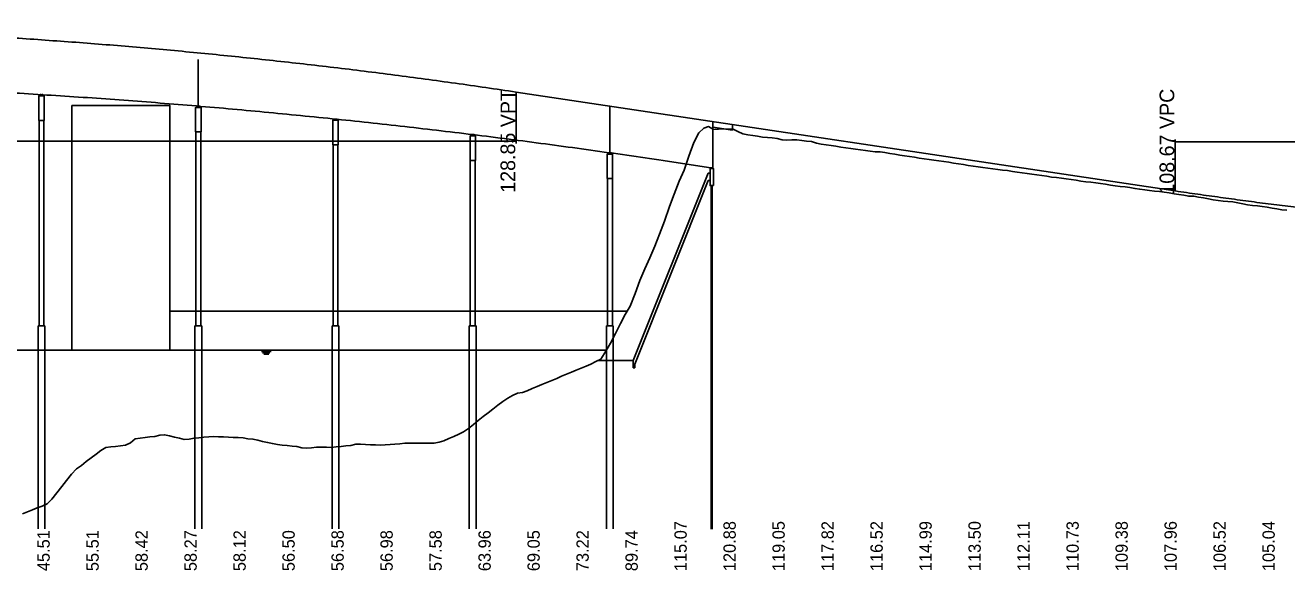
# Model space of a CAD drawing. Extents: x 2121671 to 2169879, y 557274 to 599957.
# Drawn here: x 2155742 to 2157029, y 595763 to 596320 of the extents above; entities that cross this region are included whole.
import ezdxf

# ---------------------------------------------------------------- set-up
doc = ezdxf.new("R2010")
doc.units = 0
for name, color, linetype in [('BR_CONCRETE', 7, 'Continuous'), ('BR_DETAILS', 7, 'Continuous'), ('BR_PRESTRESSED BEAM', 7, 'Continuous'), ('BR_STRUCTURAL STEEL', 7, 'Continuous'), ('RD_DDB_Profile_Elev', 7, 'Continuous'), ('RD_DDB_Profile_EX', 7, 'Continuous'), ('RD_DDB_Profile_PR', 7, 'Continuous'), ('RD_DDB_StripGrade', 7, 'Continuous'), ('RD_DDB_VCLbl', 7, 'Continuous')]:
    doc.layers.add(name, color=color, linetype=linetype)

msp = doc.modelspace()

# ---------------------------------------------------------------- linework, layer by layer
at = {"layer": 'BR_CONCRETE'}
for p, q in [((2155756.3, 596222.8), (2155756.3, 596013.1)), ((2155761.3, 596222.8), (2155761.3, 596013.1)), ((2156443.8, 596215.8), (2156463.8, 596212.8)), ((2156463.8, 596212.8), (2156463.8, 596218.6)), ((2155916.3, 596211.1), (2155916.3, 596013.1)), ((2155921.3, 596211.1), (2155921.3, 596013.1)), ((2156056.3, 596197.9), (2156056.3, 596013.1)), ((2156061.3, 596197.9), (2156061.3, 596013.1)), ((2156196.3, 596182), (2156196.3, 596013.1)), ((2156201.3, 596182), (2156201.3, 596013.1)), ((2156336.3, 596163.4), (2156336.3, 596013.1)), ((2156341.3, 596163.4), (2156341.3, 596013.1)), ((2155755.3, 596013.1), (2155755.3, 595805.8)), ((2155762.3, 596013.1), (2155762.3, 595805.8)), ((2155915.3, 596013.1), (2155915.3, 595805.8)), ((2155922.3, 596013.1), (2155922.3, 595805.8)), ((2156055.3, 596013.1), (2156055.3, 595805.8)), ((2156062.3, 596013.1), (2156062.3, 595805.8)), ((2156195.3, 596013.1), (2156195.3, 595805.8)), ((2156202.3, 596013.1), (2156202.3, 595805.8)), ((2156335.3, 596013.1), (2156335.3, 595805.8)), ((2156342.3, 596013.1), (2156342.3, 595805.8))]:
    msp.add_line(p, q, dxfattribs=at)
for points in [[(2155756.1, 596222.8), (2155761.6, 596222.8), (2155761.6, 596247.8), (2155756.1, 596247.8)], [(2155916.1, 596211.1), (2155921.6, 596211.1), (2155921.6, 596236.1), (2155916.1, 596236.1)], [(2156056.1, 596197.9), (2156061.6, 596197.9), (2156061.6, 596222.9), (2156056.1, 596222.9)], [(2156196.1, 596182), (2156201.6, 596182), (2156201.6, 596207), (2156196.1, 596207)], [(2156336.1, 596163.4), (2156341.6, 596163.4), (2156341.6, 596188.4), (2156336.1, 596188.4)], [(2156444.5, 596156.3), (2156441, 596156.3), (2156441, 596173.8), (2156444.5, 596173.8)]]:
    msp.add_lwpolyline(points, close=True, dxfattribs=at)
at = {"layer": 'BR_DETAILS'}
for p, q in [((2156362.6, 595977.7), (2156439, 596168.8)), ((2156441, 596168.8), (2156439, 596168.8)), ((2156364.1, 595974), (2156439, 596161.3)), ((2156441, 596161.3), (2156439, 596161.3)), ((2156362.6, 595977.7), (2156326.5, 595977.7)), ((2156362.6, 595977.7), (2156362.6, 595970.2)), ((2156364.1, 595970.2), (2156364.1, 595974)), ((2156362.6, 595970.2), (2156364.1, 595970.2))]:
    msp.add_line(p, q, dxfattribs=at)
for points in [[(2155757.3, 596249.1), (2155758.3, 596249.1), (2155758.3, 596247.8), (2155757.3, 596247.8)], [(2155759.3, 596249.1), (2155760.3, 596249.1), (2155760.3, 596247.8), (2155759.3, 596247.8)], [(2155917.3, 596237.3), (2155918.3, 596237.3), (2155918.3, 596236.1), (2155917.3, 596236.1)], [(2155919.3, 596237.3), (2155920.3, 596237.3), (2155920.3, 596236.1), (2155919.3, 596236.1)], [(2156057.3, 596224.2), (2156058.3, 596224.2), (2156058.3, 596222.9), (2156057.3, 596222.9)], [(2156059.3, 596224.2), (2156060.3, 596224.2), (2156060.3, 596222.9), (2156059.3, 596222.9)], [(2156197.3, 596208.3), (2156198.3, 596208.3), (2156198.3, 596207), (2156197.3, 596207)], [(2156199.3, 596208.3), (2156200.3, 596208.3), (2156200.3, 596207), (2156199.3, 596207)], [(2156337.3, 596189.7), (2156338.3, 596189.7), (2156338.3, 596188.4), (2156337.3, 596188.4)], [(2156339.3, 596189.7), (2156340.3, 596189.7), (2156340.3, 596188.4), (2156339.3, 596188.4)], [(2156442.2, 596174.2), (2156443.2, 596174.2), (2156443.2, 596173.8), (2156442.2, 596173.8)]]:
    msp.add_lwpolyline(points, close=True, dxfattribs=at)
at = {"layer": 'BR_PRESTRESSED BEAM'}
for p, q in [((2155918.8, 596237.5), (2155918.8, 596285)), ((2156338.8, 596189.9), (2156338.8, 596237.4)), ((2156443.8, 596174.1), (2156443.8, 596221.6)), ((2156393.2, 596181.7), (2156443.8, 596174.1)), ((2155755.3, 596013.1), (2155762.3, 596013.1)), ((2155915.3, 596013.1), (2155922.3, 596013.1)), ((2156055.3, 596013.1), (2156062.3, 596013.1)), ((2156195.3, 596013.1), (2156202.3, 596013.1)), ((2156335.3, 596013.1), (2156342.3, 596013.1))]:
    msp.add_line(p, q, dxfattribs=at)
msp.add_spline([(2154543.2, 596222.7), (2154580.2, 596226.6), (2154617.2, 596230.2), (2154654.2, 596233.6), (2154691.2, 596236.9), (2154728.2, 596239.9), (2154765.2, 596242.8), (2154802.2, 596245.5), (2154839.2, 596248), (2154876.2, 596250.3), (2154913.2, 596252.4), (2154950.2, 596254.3), (2154987.2, 596256), (2155024.2, 596257.6), (2155061.2, 596258.9), (2155098.2, 596260.1), (2155135.2, 596261.1), (2155172.2, 596261.9), (2155209.2, 596262.5), (2155246.2, 596262.9), (2155283.2, 596263.1), (2155320.2, 596263.1), (2155357.2, 596263), (2155394.2, 596262.6), (2155431.2, 596262.1), (2155468.2, 596261.3), (2155505.2, 596260.4), (2155542.2, 596259.3), (2155579.2, 596258), (2155616.2, 596256.5), (2155653.2, 596254.9), (2155690.2, 596253), (2155727.2, 596251), (2155764.2, 596248.7), (2155801.2, 596246.3), (2155838.2, 596243.7), (2155875.2, 596240.9), (2155912.2, 596237.9), (2155949.2, 596234.7), (2155986.2, 596231.3), (2156023.2, 596227.7), (2156060.2, 596224), (2156097.2, 596220.1), (2156134.2, 596215.9), (2156171.2, 596211.6), (2156208.2, 596207.1), (2156245.2, 596202.4), (2156282.2, 596197.5), (2156319.2, 596192.4), (2156356.2, 596187.2), (2156393.2, 596181.7)], degree=3, dxfattribs=at)
at = {"layer": 'BR_STRUCTURAL STEEL'}
for p, q in [((2156442.2, 596156.3), (2156442.2, 595805.5)), ((2156443.3, 596156.3), (2156443.3, 595805.5))]:
    msp.add_line(p, q, dxfattribs=at)
at = {"layer": 'RD_DDB_Profile_Elev'}
for p, q in [((2155889.7, 596028.1), (2156356.4, 596028.1)), ((2151972, 595988.1), (2156334.9, 595988.1)), ((2155983.2, 595986.8), (2155993.2, 595986.8)), ((2155984.4, 595985.6), (2155991.9, 595985.6)), ((2155985.7, 595984.3), (2155990.7, 595984.3))]:
    msp.add_line(p, q, dxfattribs=at)
msp.add_lwpolyline([(2155789.7, 596238.1), (2155889.7, 596238.1), (2155889.7, 595988.1), (2155789.7, 595988.1)], close=True, dxfattribs=at)
at = {"layer": 'RD_DDB_Profile_EX'}
for points in [[(2156194.5, 595908.4), (2156199.5, 595912.4), (2156204.5, 595916.4), (2156209.5, 595920.4), (2156214.5, 595924.3), (2156219.5, 595928.2), (2156224.5, 595932.1), (2156229.5, 595935.9), (2156234.5, 595939.1), (2156239.5, 595941.9), (2156244.5, 595944.4), (2156249.5, 595944.9), (2156254.5, 595946.9), (2156259.5, 595949), (2156264.5, 595951.1), (2156269.5, 595953.2), (2156274.5, 595955.3), (2156279.5, 595957.4), (2156284.5, 595959.5), (2156289.5, 595961.6), (2156294.5, 595963.7), (2156299.5, 595965.8), (2156304.5, 595967.9), (2156309.5, 595969.9), (2156314.5, 595972), (2156319.5, 595974.1), (2156324.5, 595976.7), (2156329.5, 595979.2), (2156334.5, 595987.3), (2156339.5, 595995.5), (2156344.5, 596005.2), (2156349.5, 596015.4), (2156354.5, 596024.8), (2156359.5, 596033.2), (2156364.5, 596046.1), (2156369.5, 596059.5), (2156374.5, 596071.4), (2156379.5, 596082.4), (2156384.5, 596094.5), (2156389.5, 596106.8), (2156394.5, 596120.1), (2156399.5, 596134.9), (2156404.5, 596147.6), (2156409.5, 596160.6), (2156414.5, 596172), (2156419.5, 596186.4), (2156424.5, 596200.1), (2156429.5, 596210.1), (2156434.5, 596214.9), (2156439.5, 596216.5), (2156444.5, 596213.5), (2156449.5, 596213.7), (2156454.5, 596214.2), (2156459.5, 596213.7), (2156464.5, 596213.7), (2156469.5, 596211.3), (2156474.5, 596209), (2156479.5, 596208.1), (2156484.5, 596207.4), (2156489.5, 596206.6), (2156494.5, 596205.7), (2156499.5, 596205.4), (2156504.5, 596205), (2156509.5, 596204.2), (2156514.5, 596202.8), (2156519.5, 596202.7), (2156524.5, 596202.9), (2156529.5, 596202.8), (2156534.5, 596202.1), (2156539.5, 596201.7), (2156544.5, 596201.2), (2156549.5, 596199.6), (2156554.5, 596198.5), (2156559.5, 596197.8), (2156564.5, 596197.1), (2156569.5, 596196.4), (2156574.5, 596195.4), (2156579.5, 596194.9), (2156584.5, 596194.2), (2156589.5, 596193.5), (2156594.5, 596192.9), (2156599.5, 596192.2), (2156604.5, 596191.3), (2156609.5, 596190.7), (2156614.5, 596190.7), (2156619.5, 596189.9), (2156624.5, 596189), (2156629.5, 596188.2), (2156634.5, 596187.4), (2156639.5, 596186.6), (2156644.5, 596185.8), (2156649.5, 596185.1), (2156654.5, 596184.4), (2156659.5, 596183.7), (2156664.5, 596183), (2156669.5, 596182.2), (2156674.5, 596181.5), (2156679.5, 596180.7), (2156684.5, 596180), (2156689.5, 596179.2), (2156694.5, 596178.5)], [(2156694.5, 596178.5), (2156699.5, 596177.7), (2156704.5, 596176.9), (2156709.5, 596176.2), (2156714.5, 596175.4), (2156719.5, 596174.8), (2156724.5, 596174.1), (2156729.5, 596173.5), (2156734.5, 596172.8), (2156739.5, 596172.1), (2156744.5, 596171.5), (2156749.5, 596170.7), (2156754.5, 596170), (2156759.5, 596169.4), (2156764.5, 596168.6), (2156769.5, 596167.9), (2156774.5, 596167.1), (2156779.5, 596166.4), (2156784.5, 596165.9), (2156789.5, 596165), (2156794.5, 596164.6), (2156799.5, 596163.9), (2156804.5, 596163.2), (2156809.5, 596162.5), (2156814.5, 596161.7), (2156819.5, 596160.9), (2156824.5, 596160.2), (2156829.5, 596159.6), (2156834.5, 596159), (2156839.5, 596158.4), (2156844.5, 596157.6), (2156849.5, 596156.8), (2156854.5, 596155.9), (2156859.5, 596155.3), (2156864.5, 596154.9), (2156869.5, 596154.2), (2156874.5, 596153.4), (2156879.5, 596152.5), (2156884.5, 596151.9), (2156889.5, 596151.2), (2156894.5, 596150.6), (2156899.5, 596150.1), (2156904.5, 596149.4), (2156909.5, 596148.7), (2156914.5, 596147.9), (2156919.5, 596147.1), (2156924.5, 596146.3), (2156929.5, 596145.4), (2156934.5, 596145.3), (2156939.5, 596144.5), (2156944.5, 596143.7), (2156949.5, 596142.7), (2156954.5, 596141.7), (2156959.5, 596140.9), (2156964.5, 596140.4), (2156969.5, 596140), (2156974.5, 596139.5), (2156979.5, 596138.7), (2156984.5, 596137.7), (2156989.5, 596136.6), (2156994.5, 596135.8), (2156999.5, 596135.6), (2157004.5, 596134.8), (2157009.5, 596134.1), (2157014.5, 596133.3), (2157019.5, 596132.4), (2157024.5, 596131.6), (2157029.5, 596131)], [(2155739.5, 595821.3), (2155744.5, 595823.3), (2155749.5, 595825.3), (2155754.5, 595827.2), (2155759.5, 595829.2), (2155764.5, 595831.4), (2155769.5, 595836.2), (2155774.5, 595842.6), (2155779.5, 595849), (2155784.5, 595855.3), (2155789.5, 595861.7), (2155794.5, 595867.2), (2155799.5, 595870.7), (2155804.5, 595874.5), (2155809.5, 595878.3), (2155814.5, 595882.1), (2155819.5, 595886), (2155824.5, 595888.9), (2155829.5, 595889.5), (2155834.5, 595890.1), (2155839.5, 595890.7), (2155844.5, 595891.3), (2155849.5, 595893.7), (2155854.5, 595897.9), (2155859.5, 595898.5), (2155864.5, 595899.1), (2155869.5, 595899.7), (2155874.5, 595900.3), (2155879.5, 595901.4), (2155884.5, 595902), (2155889.5, 595900.8), (2155894.5, 595899.5), (2155899.5, 595898.3), (2155904.5, 595897), (2155909.5, 595897.4), (2155914.5, 595898.5), (2155919.5, 595898.9), (2155924.5, 595899.3), (2155929.5, 595899.7), (2155934.5, 595900.2), (2155939.5, 595899.9), (2155944.5, 595899.7), (2155949.5, 595899.4), (2155954.5, 595899.2), (2155959.5, 595899), (2155964.5, 595898.7), (2155969.5, 595897.9), (2155974.5, 595897.5), (2155979.5, 595896.4), (2155984.5, 595895.2), (2155989.5, 595894.1), (2155994.5, 595892.9), (2155999.5, 595892), (2156004.5, 595891.4), (2156009.5, 595890.9), (2156014.5, 595890.4), (2156019.5, 595889.8), (2156024.5, 595888.5), (2156029.5, 595888.4), (2156034.5, 595888.7), (2156039.5, 595889.1), (2156044.5, 595889.4), (2156049.5, 595889.3), (2156054.5, 595889), (2156059.5, 595889.5), (2156064.5, 595890), (2156069.5, 595890.5), (2156074.5, 595891), (2156079.5, 595892.2), (2156084.5, 595892.3), (2156089.5, 595892.1), (2156094.5, 595891.8), (2156099.5, 595891.6), (2156104.5, 595891.4), (2156109.5, 595891.7), (2156114.5, 595892.1), (2156119.5, 595892.4), (2156124.5, 595892.8), (2156129.5, 595893.2), (2156134.5, 595893.4), (2156139.5, 595893.4), (2156144.5, 595893.4), (2156149.5, 595893.4), (2156154.5, 595893.4), (2156159.5, 595893.5), (2156164.5, 595894.4), (2156169.5, 595895.7), (2156174.5, 595898), (2156179.5, 595900.3), (2156184.5, 595902.5), (2156189.5, 595904.9), (2156194.5, 595908.4)]]:
    msp.add_lwpolyline(points, dxfattribs=at)
at = {"layer": 'RD_DDB_Profile_PR'}
msp.add_line((2156243.2, 596251.7), (2156915.7, 596150.8), dxfattribs=at)
for points in [[(2154693.2, 596286.1), (2154724.2, 596289.3), (2154755.2, 596292.3), (2154786.2, 596295.2), (2154817.2, 596297.9), (2154848.2, 596300.5), (2154879.2, 596302.9), (2154910.2, 596305.1), (2154941.2, 596307.2), (2154972.2, 596309.1), (2155003.2, 596310.9), (2155034.2, 596312.5), (2155065.2, 596314), (2155096.2, 596315.3), (2155127.2, 596316.4), (2155158.2, 596317.4), (2155189.2, 596318.2), (2155220.2, 596318.9), (2155251.2, 596319.4), (2155282.2, 596319.7), (2155313.2, 596319.9), (2155344.2, 596319.9), (2155375.2, 596319.8), (2155406.2, 596319.5), (2155437.2, 596319), (2155468.2, 596318.4), (2155499.2, 596317.7), (2155530.2, 596316.7), (2155561.2, 596315.7), (2155592.2, 596314.4), (2155623.2, 596313), (2155654.2, 596311.4), (2155685.2, 596309.7), (2155716.2, 596307.9), (2155747.2, 596305.8), (2155778.2, 596303.6), (2155809.2, 596301.3), (2155840.2, 596298.8), (2155871.2, 596296.1), (2155902.2, 596293.3), (2155933.2, 596290.3), (2155964.2, 596287.1), (2155995.2, 596283.8), (2156026.2, 596280.4), (2156057.2, 596276.8), (2156088.2, 596273), (2156119.2, 596269), (2156150.2, 596264.9), (2156181.2, 596260.7), (2156212.2, 596256.3), (2156243.2, 596251.7)], [(2156915.7, 596150.8), (2156927.2, 596149.1), (2156938.7, 596147.4), (2156950.2, 596145.8), (2156961.7, 596144.2), (2156973.2, 596142.6), (2156984.7, 596141.1), (2156996.2, 596139.5), (2157007.7, 596138.1), (2157019.2, 596136.6), (2157030.7, 596135.2), (2157042.2, 596133.8), (2157053.7, 596132.4), (2157065.2, 596131.1), (2157076.7, 596129.8), (2157088.2, 596128.5), (2157099.7, 596127.3), (2157111.2, 596126.1), (2157122.7, 596124.9), (2157134.2, 596123.8), (2157145.7, 596122.7), (2157157.2, 596121.6), (2157168.7, 596120.6), (2157180.2, 596119.6), (2157191.7, 596118.6), (2157203.2, 596117.7), (2157214.7, 596116.8), (2157226.2, 596115.9), (2157237.7, 596115), (2157249.2, 596114.2), (2157260.7, 596113.4), (2157272.2, 596112.7), (2157283.7, 596112), (2157295.2, 596111.3), (2157306.7, 596110.6), (2157318.2, 596110), (2157329.7, 596109.4), (2157341.2, 596108.8), (2157352.7, 596108.3), (2157364.2, 596107.8), (2157375.7, 596107.3), (2157387.2, 596106.9), (2157398.7, 596106.5), (2157410.2, 596106.1), (2157421.7, 596105.8), (2157433.2, 596105.5), (2157444.7, 596105.2), (2157456.2, 596105), (2157467.7, 596104.8), (2157479.2, 596104.6), (2157490.7, 596104.4)]]:
    msp.add_spline(points, degree=3, dxfattribs=at)
at = {"layer": 'RD_DDB_VCLbl'}
for p, q in [((2156243.2, 596199.2), (2156243.2, 596251.7)), ((2156915.7, 596203.3), (2156915.7, 596150.8)), ((2154693.2, 596201.7), (2156243.2, 596201.7)), ((2156915.7, 596200.8), (2157490.7, 596200.8))]:
    msp.add_line(p, q, dxfattribs=at)

# ---------------------------------------------------------------- texts
at = {"layer": 'RD_DDB_StripGrade'}
for s, height, p in [('108.67 VPC', 15, (2156914.7, 596147)), ('128.85 VPT', 15, (2156242.2, 596148.9)), ('56.50', 12.5, (2156017.2, 595762.7)), ('69.05', 12.5, (2156267.2, 595762.7)), ('89.74', 12.5, (2156367.2, 595762.7)), ('115.07', 12.5, (2156417.2, 595762.7)), ('120.88', 12.5, (2156467.2, 595762.7)), ('119.05', 12.5, (2156517.2, 595762.7)), ('117.82', 12.5, (2156567.2, 595762.7)), ('116.52', 12.5, (2156617.2, 595762.7)), ('114.99', 12.5, (2156667.2, 595762.7)), ('113.50', 12.5, (2156717.2, 595762.7)), ('112.11', 12.5, (2156767.2, 595762.7)), ('110.73', 12.5, (2156817.2, 595762.7)), ('109.38', 12.5, (2156867.2, 595762.7)), ('107.96', 12.5, (2156917.2, 595762.7)), ('106.52', 12.5, (2156967.2, 595762.7)), ('105.04', 12.5, (2157017.2, 595762.7)), ('45.51', 12.5, (2155767.2, 595762.7)), ('55.51', 12.5, (2155817.2, 595762.7)), ('58.42', 12.5, (2155867.2, 595762.7)), ('58.27', 12.5, (2155917.2, 595762.7)), ('58.12', 12.5, (2155967.2, 595762.7)), ('56.58', 12.5, (2156067.2, 595762.7)), ('56.98', 12.5, (2156117.2, 595762.7)), ('57.58', 12.5, (2156167.2, 595762.7)), ('63.96', 12.5, (2156217.2, 595762.7)), ('73.22', 12.5, (2156317.2, 595762.7))]:
    msp.add_text(s, height=height, rotation=90, dxfattribs=at).set_placement(p)

doc.saveas('drawing.dxf')
